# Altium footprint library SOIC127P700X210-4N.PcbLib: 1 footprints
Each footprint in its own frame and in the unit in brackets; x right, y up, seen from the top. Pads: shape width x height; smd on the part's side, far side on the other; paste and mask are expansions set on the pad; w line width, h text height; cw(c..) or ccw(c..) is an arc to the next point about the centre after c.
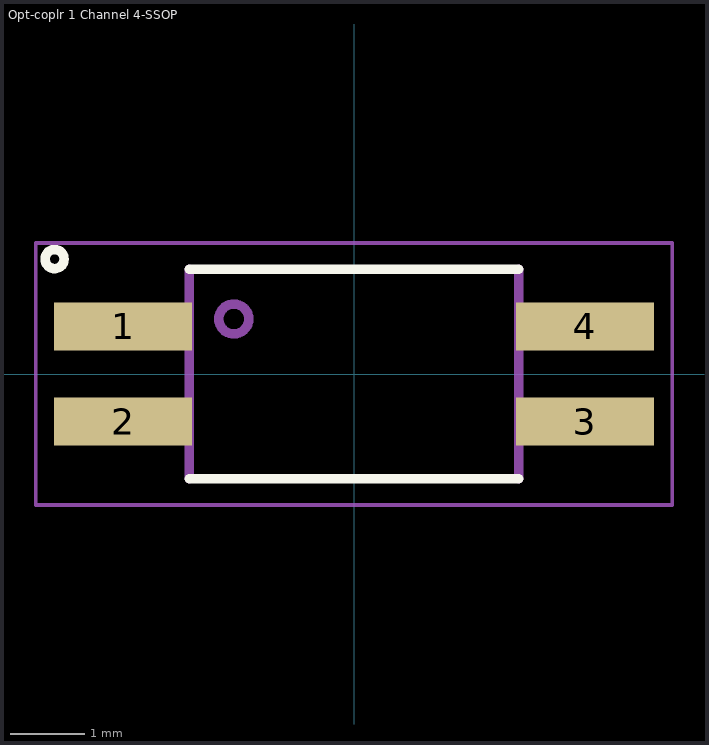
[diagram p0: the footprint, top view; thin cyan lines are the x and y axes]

## Opt-coplr 1 Channel 4-SSOP [mm] "Opt-coplr 1 Channel 4-SSOP SMT VOS617A-8X001T"
pads (4):
  rect 1.84x0.64 smd: 1(-3.085,0.635) 2(-3.085,-0.635) 3(3.085,-0.635) 4(3.085,0.635)
Top Overlay:
  circle w0.127: c-3.999,1.535 r0.127
  lines w0.127: -2.2,-1.4 2.2,-1.4 ; -2.2,1.4 2.2,1.4
Mechanical 13:
  circle w0.127: c-1.605,0.735 r0.2
  lines w0.127: -2.2,-1.4 -2.2,1.4 ; 2.2,-1.4 2.2,1.4
Mechanical 15:
  lines w0.05: -4.25,-1.75 -4.25,1.75 4.25,1.75 4.25,-1.75 -4.25,-1.75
